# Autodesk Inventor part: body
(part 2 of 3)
sketch "Sketch106"
  geometry: L1 (112.535, 34.634)-(92.5, 34.634) reference; L2 (92.5, 34.634)-(74.5, 34.634) reference; L3 (74.5, 34.634)-(74.5, 30.196) reference; L4 (134.5, 30.196)-(74.5, 30.196) reference; L5 (134.5, 30.196)-(134.5, 10.853) reference; L6 (134.5, 10.853)-(131.5, 10.853) reference; L7 (131.5, 10.853)-(9.5, 10.853) reference; L8 (9.5, 10.853)-(6.5, 10.853) reference; L9 (6.5, 10.853)-(6.5, 30.196) reference; L10 (66.5, 30.196)-(6.5, 30.196) reference; L11 (66.5, 30.196)-(66.5, 34.634) reference; L12 (66.5, 34.634)-(48.5, 34.634) reference; L13 (48.5, 34.634)-(28.5, 34.634) reference; L14 (28.5, 34.634)-(28.5, 41.393) reference; L15 (28.5, 41.393)-(26.5, 41.393) reference; L16 (26.5, 41.393)-(26.5, 57.363) reference; L17 (26.5, 57.363)-(25.5, 57.363) reference; L18 (25.5, 57.363)-(25.5, 59.786) reference; L19 (25.5, 59.786)-(22.531, 56.13) reference; L20 (22.531, 56.13)-(18.537, 61.042) reference; L21 (18.537, 61.042)-(16.572, 63.459) reference; L22 (21.463, 69.48)-(16.572, 63.459) reference; L23 (22.049, 70.202)-(21.463, 69.48) reference; L24 (27.031, 76.338)-(22.049, 70.202) reference; L25 (27.852, 77.348)-(27.031, 76.338) reference; L26 (33.05, 83.749)-(27.852, 77.348) reference; L27 (33.757, 84.619)-(33.05, 83.749) reference; L28 (38.706, 90.712)-(33.757, 84.619) reference; L29 (39.413, 91.583)-(38.706, 90.712) reference; L30 (45.068, 98.547)-(39.413, 91.583) reference; L31 (45.775, 99.417)-(45.068, 98.547) reference; L32 (51.007, 105.86)-(45.775, 99.417) reference; L33 (51.711, 106.726)-(51.007, 105.86) reference; L34 (57.086, 113.344)-(51.711, 106.726) reference; L35 (57.793, 114.215)-(57.086, 113.344) reference; L36 (63.448, 121.179)-(57.793, 114.215) reference; L37 (64.155, 122.049)-(63.448, 121.179) reference; L38 (70.517, 129.883)-(64.155, 122.049) reference; L39 (70.517, 129.883)-(76.883, 122.053) reference; L40 (76.883, 122.053)-(77.59, 121.183) reference; L41 (77.59, 121.183)-(83.249, 114.223) reference; L42 (83.249, 114.223)-(83.956, 113.353) reference; L43 (83.956, 113.353)-(89.33, 106.743) reference; L44 (89.33, 106.743)-(90.037, 105.873) reference; L45 (90.037, 105.873)-(95.272, 99.433) reference; L46 (95.272, 99.433)-(95.98, 98.563) reference; L47 (95.98, 98.563)-(101.594, 91.656) reference; L48 (101.594, 91.656)-(102.302, 90.786) reference; L49 (102.302, 90.786)-(107.296, 84.642) reference; L50 (107.296, 84.642)-(108.004, 83.772) reference; L51 (108.004, 83.772)-(113.283, 77.279) reference; L52 (113.283, 77.279)-(113.99, 76.409) reference; L53 (113.99, 76.409)-(119.036, 70.202) reference; L54 (119.036, 70.202)-(119.743, 69.332) reference; L55 (119.743, 69.332)-(124.5, 63.48) reference; L56 (124.5, 63.48)-(122.529, 61.052) reference; L57 (122.529, 61.052)-(118.531, 56.13) reference; L58 (118.531, 56.13)-(115.5, 59.858) reference; L59 (115.5, 59.858)-(115.5, 56.973) reference; L60 (115.5, 56.973)-(114.5, 56.973) reference; L61 (114.5, 56.973)-(114.5, 41.452) reference; L62 (114.5, 41.452)-(112.535, 41.452) reference; L63 (112.535, 41.452)-(112.535, 34.634) reference; L64 (141, 136)-(0, 136)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; 3 further points
  constraints: 146 end point, 46 horizontal, 26 point on line, 15 parallel, 11 perpendicular, 2 midpoint, 78 other
extrude "Extrusion106" cut sketch "Sketch106" distance "d229" = 0.5; taper "d230" = 0 deg
sketch "Sketch107"
  geometry: L1 (0, -7.179)-(141, -7.179); L2 (141, -8)-(0, -8); L3 (0, -14)-(141, -14); L4 (141, -15.001)-(0, -15.001); L5 (0, -20.711)-(141, -20.711); L6 (141, -21.45)-(0, -21.45); L7 (0, -28.164)-(141, -28.164); L8 (141, -29.014)-(0, -29.014); L9 (0, -35.384)-(141, -35.384); L10 (141, -36.288)-(0, -36.288); 5 further points
  constraints: 20 end point, 10 horizontal, 22 other
extrude "Extrusion107" cut sketch "Sketch107" distance "d231" = 0.5; taper "d232" = 0 deg
sketch "Sketch108"
  geometry: L1 (0, -7.421)-(141, -7.421) reference; L2 (141, 0)-(0, 0) reference; L3 (7.47, 0)-(7.854, 0); L4 (7.854, 0)-(7.854, -7.421); L5 (7.854, -7.421)-(7.47, -7.421); L6 (7.47, -7.421)-(7.47, 0); L7 (15.615, 0)-(16, 0); L8 (16, 0)-(16, -7.421); L9 (16, -7.421)-(15.615, -7.421); L10 (15.615, -7.421)-(15.615, 0); L11 (23.615, 0)-(24, 0); L12 (24, 0)-(24, -7.421); L13 (24, -7.421)-(23.615, -7.421); L14 (23.615, -7.421)-(23.615, 0); L15 (31.615, 0)-(32, 0); L16 (32, 0)-(32, -7.421); L17 (32, -7.421)-(31.615, -7.421); L18 (31.615, -7.421)-(31.615, 0); L19 (39.615, 0)-(40, 0); L20 (40, 0)-(40, -7.421); L21 (40, -7.421)-(39.615, -7.421); L22 (39.615, -7.421)-(39.615, 0); L23 (47.615, 0)-(48, 0); L24 (48, 0)-(48, -7.421); L25 (48, -7.421)-(47.615, -7.421); L26 (47.615, -7.421)-(47.615, 0); L27 (55.615, 0)-(56, 0); L28 (56, 0)-(56, -7.421); L29 (56, -7.421)-(55.615, -7.421); L30 (55.615, -7.421)-(55.615, 0); L31 (63.615, 0)-(64, 0); L32 (64, 0)-(64, -7.421); L33 (64, -7.421)-(63.615, -7.421); L34 (63.615, -7.421)-(63.615, 0); L35 (71.615, 0)-(72, 0); L36 (72, 0)-(72, -7.421); L37 (72, -7.421)-(71.615, -7.421); L38 (71.615, -7.421)-(71.615, 0); L39 (79.615, 0)-(80, 0); L40 (80, 0)-(80, -7.421); L41 (80, -7.421)-(79.615, -7.421); L42 (79.615, -7.421)-(79.615, 0); L43 (87.615, 0)-(88, 0); L44 (88, 0)-(88, -7.421); L45 (88, -7.421)-(87.615, -7.421); L46 (87.615, -7.421)-(87.615, 0); L47 (95.615, 0)-(96, 0); L48 (96, 0)-(96, -7.421); L49 (96, -7.421)-(95.615, -7.421); L50 (95.615, -7.421)-(95.615, 0); L51 (103.615, 0)-(104, 0); L52 (104, 0)-(104, -7.421); L53 (104, -7.421)-(103.615, -7.421); L54 (103.615, -7.421)-(103.615, 0); L55 (111.615, 0)-(112, 0); L56 (112, 0)-(112, -7.421); L57 (112, -7.421)-(111.615, -7.421); L58 (111.615, -7.421)-(111.615, 0); L59 (119.615, 0)-(120, 0); L60 (120, 0)-(120, -7.421); L61 (120, -7.421)-(119.615, -7.421); L62 (119.615, -7.421)-(119.615, 0); L63 (126.62, 0)-(127.004, 0); L64 (127.004, 0)-(127.004, -7.421)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; 1 further point
  constraints: 136 end point, 34 parallel, 17 horizontal, 17 perpendicular, 2 point on line
extrude "Extrusion108" cut sketch "Sketch108" distance "d233" = 0.5; taper "d234" = 0 deg
sketch "Sketch109"
  geometry: L1 (6.945, 6.642)-(7.33, 6.642); L2 (7.33, 6.642)-(7.33, 0); L3 (7.33, 0)-(6.945, 0); L4 (6.945, 0)-(6.945, 6.642); L5 (13.996, 6.642)-(14.38, 6.642); L6 (14.38, 6.642)-(14.38, 0); L7 (14.38, 0)-(13.996, 0); L8 (13.996, 0)-(13.996, 6.642); L9 (21, 6.642)-(21.385, 6.642); L10 (21.385, 6.642)-(21.385, 0); L11 (21.385, 0)-(21, 0); L12 (21, 0)-(21, 6.642); L13 (29, 6.642)-(29.385, 6.642); L14 (29.385, 6.642)-(29.385, 0); L15 (29.385, 0)-(29, 0); L16 (29, 0)-(29, 6.642); L17 (37, 6.642)-(37.385, 6.642); L18 (37.385, 6.642)-(37.385, 0); L19 (37.385, 0)-(37, 0); L20 (37, 0)-(37, 6.642); L21 (45, 6.642)-(45.385, 6.642); L22 (45.385, 6.642)-(45.385, 0); L23 (45.385, 0)-(45, 0); L24 (45, 0)-(45, 6.642); L25 (53, 6.642)-(53.385, 6.642); L26 (53.385, 6.642)-(53.385, 0); L27 (53.385, 0)-(53, 0); L28 (53, 0)-(53, 6.642); L29 (61, 6.642)-(61.385, 6.642); L30 (61.385, 6.642)-(61.385, 0); L31 (61.385, 0)-(61, 0); L32 (61, 0)-(61, 6.642); L33 (69, 6.642)-(69.385, 6.642); L34 (69.385, 6.642)-(69.385, 0); L35 (69.385, 0)-(69, 0); L36 (69, 0)-(69, 6.642); L37 (77, 6.642)-(77.385, 6.642); L38 (77.385, 6.642)-(77.385, 0); L39 (77.385, 0)-(77, 0); L40 (77, 0)-(77, 6.642); L41 (85, 6.642)-(85.385, 6.642); L42 (85.385, 6.642)-(85.385, 0); L43 (85.385, 0)-(85, 0); L44 (85, 0)-(85, 6.642); L45 (93, 6.642)-(93.385, 6.642); L46 (93.385, 6.642)-(93.385, 0); L47 (93.385, 0)-(93, 0); L48 (93, 0)-(93, 6.642); L49 (101, 6.642)-(101.385, 6.642); L50 (101.385, 6.642)-(101.385, 0); L51 (101.385, 0)-(101, 0); L52 (101, 0)-(101, 6.642); L53 (109, 6.642)-(109.385, 6.642); L54 (109.385, 6.642)-(109.385, 0); L55 (109.385, 0)-(109, 0); L56 (109, 0)-(109, 6.642); L57 (117, 6.642)-(117.385, 6.642); L58 (117.385, 6.642)-(117.385, 0); L59 (117.385, 0)-(117, 0); L60 (117, 0)-(117, 6.642); L61 (125, 6.642)-(125.385, 6.642); L62 (125.385, 6.642)-(125.385, 0); L63 (125.385, 0)-(125, 0); L64 (125, 0)-(125, 6.642)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; 3 further points
  constraints: 136 end point, 34 parallel, 17 horizontal, 17 perpendicular, 18 other
extrude "Extrusion109" cut sketch "Sketch109" distance "d235" = 0.5; taper "d236" = 0 deg
fillet "Fillet1" dims "d237" = 1.5
sketch "Sketch110"
  geometry: L1 (-25.92, 44.197)-(-26.502, 43.385) reference; L2 (-105.601, -66.016)-(-100, -70.035) reference; L3 (-100, -70.035)-(-22, 38.693) reference; L4 (0, 4.693)-(0, 16.519) reference; L5 (-2.706, 19.781)-(-3.198, 20.54) reference; L6 (-18.1, 44.492)-(-20.805, 48.671) reference; L7 (-2.706, 19.781)-(0, 15.598); L8 (-3.198, 20.54)-(-21.049, 48.128); L9 (-21.888, 48.585)-(-22.259, 48.585); L10 (-23.071, 48.168)-(-25.92, 44.197); L11 (-26.502, 43.385)-(-105.195, -66.308); L12 (-104.917, -66.507)-(-22.881, 47.846); L13 (-22.068, 48.263)-(-22.042, 48.263); L14 (-21.203, 47.806)-(0, 15.038); A1 r 1 centre (-22.068, 47.263) between (-22.068, 48.263) and (-22.881, 47.846); A2 r 1 centre (-22.042, 47.263) between (-21.203, 47.806) and (-22.042, 48.263); A3 r 1 centre (-21.888, 47.585) between (-21.049, 48.128) and (-21.888, 48.585); A4 r 1 centre (-22.259, 47.585) between (-22.259, 48.585) and (-23.071, 48.168); 1 further point
  constraints: 16 end point, 8 point on circle, 8 tangent, 5 parallel, 4 centre point, 4 point on line, 3 equal radius, 2 perpendicular, 1 collinear
  dimensions: "d238" = 1 radius of A1
extrude "Extrusion110" cut sketch "Sketch110" distance "d239" = 0.5; taper "d240" = 0 deg
sketch "Sketch111"
  geometry: L1 (-66.098, 27.153)-(-66.684, 26.567) reference; L2 (-71.928, 22.028)-(-67.998, 18.1) reference; L3 (32.057, 18.1)-(36, 22.045) reference; L4 (-11.617, 69.638)-(-17.983, 76) reference; L5 (-66.684, 26.567)-(-71.574, 21.674); L6 (-66.098, 27.153)-(-19.397, 73.878); L7 (-16.568, 73.879)-(35.646, 21.691); L8 (35.415, 21.459)-(-16.585, 73.432); L9 (-19.413, 73.432)-(-71.359, 21.459); L10 (-71.574, 21.674)-(-71.359, 21.459); A1 r 2 centre (-17.999, 72.018) between (-16.585, 73.432) and (-19.413, 73.432); A2 r 2 centre (-17.982, 72.464) between (-16.568, 73.879) and (-19.397, 73.878); 1 further point
  constraints: 12 end point, 5 perpendicular, 4 point on circle, 4 point on line, 4 tangent, 2 centre point, 1 collinear, 1 equal radius
  dimensions: "d241" = 2 radius of A1
extrude "Extrusion111" cut sketch "Sketch111" distance "d242" = 0.5; taper "d243" = 0 deg
sketch "Sketch112"
  geometry: L1 (9, 0)-(9, 60.457) reference; L2 (2.125, 63.944)-(9, 60.457) reference; L3 (0, 65.022)-(0, 0) reference; L4 (9, 0)-(0, 0) reference; L5 (9, 6)-(0, 6); L6 (0, 6)-(0, 6.417); L7 (0, 6.417)-(9, 6.417); L8 (9, 6.417)-(9, 6); L9 (9, 12.583)-(0, 12.583); L10 (0, 12.583)-(0, 13); L11 (0, 13)-(9, 13); L12 (9, 13)-(9, 12.583); L13 (9, 19.583)-(0, 19.583); L14 (0, 19.583)-(0, 20); L15 (0, 20)-(9, 20); L16 (9, 20)-(9, 19.583); L17 (9, 26.583)-(0, 26.583); L18 (0, 26.583)-(0, 27); L19 (0, 27)-(9, 27); L20 (9, 27)-(9, 26.583); L21 (9, 33.583)-(0, 33.583); L22 (0, 33.583)-(0, 34); L23 (0, 34)-(9, 34); L24 (9, 34)-(9, 33.583); L25 (9, 40.583)-(0, 40.583); L26 (0, 40.583)-(0, 41); L27 (0, 41)-(9, 41); L28 (9, 41)-(9, 40.583); L29 (9, 47.519)-(0, 47.519); L30 (0, 47.519)-(0, 47.936); L31 (0, 47.936)-(9, 47.936); L32 (9, 47.936)-(9, 47.519); L33 (9, 54.413)-(0, 54.413); L34 (0, 54.413)-(0, 54.83); L35 (0, 54.83)-(9, 54.83); L36 (9, 54.83)-(9, 54.413); L37 (7.718, 61.108)-(0, 61.108); L38 (0, 61.108)-(0, 61.429); L39 (0, 61.429)-(7.085, 61.429); 1 further point
  constraints: 70 end point, 18 parallel, 9 horizontal, 9 perpendicular, 4 point on line
extrude "Extrusion112" cut sketch "Sketch112" distance "d244" = 0.5; taper "d245" = 0 deg
sketch "Sketch113"
  geometry: L1 (-0.653, 8.5)-(-0.974, 8.5) reference; L2 (-3.422, 6.744)-(0, 0) reference; L3 (0, 0)-(60.455, 0) reference; L4 (12.936, 9)-(19.455, 9) reference; L5 (-0.974, 8.5)-(-0.974, 1.919); L6 (5.625, 8.5)-(6.042, 8.5); L7 (6.042, 8.5)-(6.042, 0); L8 (6.042, 0)-(5.625, 0); L9 (5.625, 0)-(5.625, 8.5); L10 (12.519, 8.5)-(12.936, 8.5); L11 (12.936, 8.5)-(12.936, 0); L12 (12.936, 0)-(12.519, 0); L13 (12.519, 0)-(12.519, 8.5); L14 (19.455, 8.5)-(19.872, 8.5); L15 (19.872, 8.5)-(19.872, 0); L16 (19.872, 0)-(19.455, 0); L17 (19.455, 0)-(19.455, 8.5); L18 (26.455, 8.5)-(26.883, 8.5); L19 (26.883, 0)-(26.455, 0); L20 (34, 0)-(33.455, 0); L21 (41, 0)-(40.455, 0); L22 (47.455, 8.5)-(47.872, 8.5); L23 (47.872, 8.5)-(47.872, 0); L24 (47.872, 0)-(47.455, 0); L25 (47.455, 0)-(47.455, 8.5); L26 (54.038, 8.5)-(54.455, 8.5); L27 (54.455, 8.5)-(54.455, 0); L28 (54.455, 0)-(54.038, 0); L29 (54.038, 0)-(54.038, 8.5); L30 (-0.653, 8.5)-(-0.653, 1.286); L31 (26.455, 8.5)-(26.883, 8.5); L32 (26.883, 8.5)-(26.883, 0); L33 (26.883, 0)-(26.455, 0); L34 (26.455, 0)-(26.455, 8.5); L35 (33.455, 8.5)-(33.872, 8.5); L36 (33.872, 8.5)-(33.872, 0); L37 (33.872, 0)-(33.455, 0); L38 (33.455, 0)-(33.455, 8.5); L39 (40.455, 8.5)-(40.872, 8.5); L40 (40.872, 8.5)-(40.872, 0); L41 (40.872, 0)-(40.455, 0); L42 (40.455, 0)-(40.455, 8.5); 1 further point
  constraints: 76 end point, 18 parallel, 9 horizontal, 9 perpendicular, 9 point on line
extrude "Extrusion113" cut sketch "Sketch113" distance "d246" = 0.5; taper "d247" = 0 deg
fillet "Fillet2" dims "d248" = 1.5
fillet "Fillet3" dims "d249" = 0.5, "d250" = 1.5
sketch "Sketch114"
  geometry: L1 (7, -17.145)-(7, -25.258) reference; L2 (1, -25.258)-(1, -17.145) reference; L3 (-60, -50.112)-(-60, 7.159) reference; L4 (68, 7.159)-(68, -50.112) reference; L5 (-60, 0)-(68, 0); L6 (68, 0)-(68, -1); L7 (68, -1)-(-60, -1); L8 (-60, -1)-(-60, 0); L9 (-60, -9)-(68, -9); L10 (68, -9)-(68, -10); L11 (68, -10)-(-60, -10); L12 (-60, -10)-(-60, -9); L13 (-60, -18)-(1, -18); L14 (1, -18)-(1, -19); L15 (1, -19)-(-60, -19); L16 (-60, -19)-(-60, -18); L17 (7, -18)-(68, -18); L18 (68, -18)-(68, -19); L19 (68, -19)-(7, -19); L20 (7, -19)-(7, -18); L21 (-60, -27)-(68, -27); L22 (68, -27)-(68, -28); L23 (68, -28)-(-60, -28); L24 (-60, -28)-(-60, -27); L25 (-60, -36)-(68, -36); L26 (68, -36)-(68, -37); L27 (68, -37)-(-60, -37); L28 (-60, -37)-(-60, -36); L29 (-60, -45)-(68, -45); L30 (68, -45)-(68, -46); L31 (68, -46)-(-60, -46); L32 (-60, -46)-(-60, -45); 1 further point
  constraints: 56 end point, 14 parallel, 14 point on line, 7 horizontal, 7 perpendicular
extrude "Extrusion114" cut sketch "Sketch114" distance "d251" = 0.5; taper "d252" = 0 deg
sketch "Sketch115"
  geometry: L1 (-119.015, -55.796)-(-118.805, -56.25) reference; L2 (-118.805, -56.25)-(-119.713, -56.669) reference; L3 (-119.713, -56.669)-(-119.923, -56.215) reference; L4 (-119.923, -56.215)-(-127.187, -59.567) reference; L5 (-127.187, -59.567)-(-126.977, -60.021) reference; L6 (-126.977, -60.021)-(-127.885, -60.44) reference; L7 (-127.885, -60.44)-(-128.094, -59.986) reference; L8 (-128.094, -59.986)-(-135.358, -63.339) reference; L9 (-135.358, -63.339)-(-135.149, -63.793) reference; L10 (-135.149, -63.793)-(-136.057, -64.212) reference; L11 (-136.057, -64.212)-(-136.266, -63.758) reference; L12 (-136.266, -63.758)-(-140, -65.481) reference; L13 (-140, -65.481)-(-136, -74.148) reference; L14 (-94.526, -50.578)-(-98.786, -56.517) reference; L15 (-94.526, -50.578)-(-94.12, -50.87) reference; L16 (-94.12, -50.87)-(-93.537, -50.057) reference; L17 (-93.943, -49.766)-(-93.537, -50.057) reference; L18 (-89.863, -44.078)-(-93.943, -49.766) reference; L19 (-89.863, -44.078)-(-89.457, -44.369) reference; L20 (-89.457, -44.369)-(-88.874, -43.557) reference; L21 (-89.28, -43.265)-(-88.874, -43.557) reference; L22 (-88, -41.481)-(-89.28, -43.265) reference; L23 (-88, -41.481)-(-94.5, -44.481) reference; L24 (-94.5, -44.481)-(-94.29, -44.935) reference; L25 (-94.29, -44.935)-(-95.198, -45.354) reference; L26 (-95.198, -45.354)-(-95.408, -44.9) reference; L27 (-95.408, -44.9)-(-102.672, -48.253) reference; L28 (-102.672, -48.253)-(-102.462, -48.707) reference; L29 (-102.462, -48.707)-(-103.37, -49.126) reference; L30 (-103.37, -49.126)-(-103.58, -48.672) reference; L31 (-103.58, -48.672)-(-110.843, -52.024) reference; L32 (-110.843, -52.024)-(-110.634, -52.478) reference; L33 (-110.634, -52.478)-(-111.542, -52.897) reference; L34 (-111.542, -52.897)-(-111.751, -52.443) reference; L35 (-111.751, -52.443)-(-119.015, -55.796) reference; L36 (-137, -71.981)-(-96.656, -53.547); 1 further point
  constraints: 2 end point, 1 midpoint, 1 point on line
extrude "Extrusion115" join sketch "Sketch115" distance "d253" = 0.5; taper "d254" = 0 deg
sketch "Sketch116"
  geometry: L1 (118.805, -56.233)-(119.015, -55.779) reference; L2 (119.015, -55.779)-(111.751, -52.427) reference; L3 (111.751, -52.427)-(111.542, -52.881) reference; L4 (111.542, -52.881)-(110.634, -52.462) reference; L5 (110.634, -52.462)-(110.843, -52.008) reference; L6 (110.843, -52.008)-(103.58, -48.655) reference; L7 (103.58, -48.655)-(103.37, -49.109) reference; L8 (103.37, -49.109)-(102.462, -48.69) reference; L9 (102.462, -48.69)-(102.672, -48.236) reference; L10 (102.672, -48.236)-(95.408, -44.884) reference; L11 (95.408, -44.884)-(95.198, -45.338) reference; L12 (95.198, -45.338)-(94.29, -44.919) reference; L13 (94.29, -44.919)-(94.5, -44.465) reference; L14 (94.5, -44.465)-(88, -41.465) reference; L15 (89.28, -43.249)-(88, -41.465) reference; L16 (89.28, -43.249)-(88.874, -43.54) reference; L17 (88.874, -43.54)-(89.457, -44.353) reference; L18 (89.863, -44.061)-(89.457, -44.353) reference; L19 (93.943, -49.749)-(89.863, -44.061) reference; L20 (93.943, -49.749)-(93.537, -50.041) reference; L21 (93.537, -50.041)-(94.12, -50.853) reference; L22 (94.526, -50.562)-(94.12, -50.853) reference; L23 (98.786, -56.5)-(94.526, -50.562) reference; L24 (136, -74.131)-(140, -65.465) reference; L25 (140, -65.465)-(136.266, -63.741) reference; L26 (136.266, -63.741)-(136.057, -64.195) reference; L27 (136.057, -64.195)-(135.149, -63.776) reference; L28 (135.149, -63.776)-(135.358, -63.322) reference; L29 (135.358, -63.322)-(128.094, -59.97) reference; L30 (128.094, -59.97)-(127.885, -60.424) reference; L31 (127.885, -60.424)-(126.977, -60.005) reference; L32 (126.977, -60.005)-(127.187, -59.551) reference; L33 (127.187, -59.551)-(119.923, -56.198) reference; L34 (119.923, -56.198)-(119.713, -56.652) reference; L35 (119.713, -56.652)-(118.805, -56.233) reference; L36 (136.984, -72)-(96.656, -53.531); 1 further point
  constraints: 2 end point, 1 midpoint, 1 point on line
extrude "Extrusion116" join sketch "Sketch116" distance "d255" = 0.5; taper "d256" = 0 deg
sketch "Sketch117"
  geometry: L1 (89.28, -43.249)-(88, -41.465) reference; L2 (136.984, -72)-(140, -65.465) reference; L3 (136.057, -64.195)-(135.149, -63.776) reference; L4 (136.057, -64.195)-(139.79, -65.919); L5 (139.565, -66.408)-(89.28, -43.249); L6 (119.713, -56.652)-(118.805, -56.233) reference; L7 (135.149, -63.776)-(88.591, -42.288); L8 (88.591, -42.288)-(89.28, -43.249); 2 further points
  constraints: 8 end point, 3 point on line, 2 collinear, 1 midpoint, 1 perpendicular
extrude "Extrusion117" cut sketch "Sketch117" distance "d257" = 0.5; taper "d258" = 0 deg
sketch "Sketch118"
  geometry: L1 (-135.149, -63.793)-(-136.057, -64.212) reference; L2 (-140, -65.481)-(-137, -71.981) reference; L3 (-88, -41.481)-(-89.28, -43.265) reference; L4 (-136.057, -64.212)-(-139.79, -65.935); L5 (-135.149, -63.793)-(-88.487, -42.159); L6 (-139.571, -66.412)-(-89.098, -43.012); 1 further point
  constraints: 6 end point, 4 point on line, 1 parallel, 1 perpendicular
extrude "Extrusion118" cut sketch "Sketch118" distance "d259" = 0.5; taper "d260" = 0 deg
sketch "Sketch119"
  geometry: L1 (125, 1.52)-(125, 2.045) reference; L2 (-3, 2.045)-(-3, 1.507) reference; L3 (125, 1.52)-(-3, 1.507); L4 (-3, 2.045)-(125, 2.045); 1 further point
  constraints: 4 end point
extrude "Extrusion119" cut sketch "Sketch119" distance "d261" = 0.5; taper "d262" = 0 deg
sketch "Sketch120"
  geometry: L1 (0, 16.535)-(0, 3.214) reference; L2 (0, 3.214)-(22.527, 38.028) reference; L3 (100.026, -70)-(105.601, -66) reference; L4 (102.863, -63.041)-(102.281, -62.229) reference; L5 (102.863, -63.041)-(105.195, -66.291); L6 (102.281, -62.229)-(25.92, 44.214); L7 (18.52, 44.237)-(0, 15.615); L8 (0, 15)-(21.239, 47.824); L9 (22.078, 48.28)-(22.106, 48.28); L10 (22.918, 47.863)-(104.942, -66.473); L11 (18.52, 44.237)-(21.04, 48.131); L12 (21.879, 48.587)-(22.269, 48.587); L13 (23.081, 48.17)-(25.92, 44.214); A1 r 1 centre (22.078, 47.28) between (22.078, 48.28) and (21.239, 47.824); A2 r 1 centre (22.106, 47.28) between (22.918, 47.863) and (22.106, 48.28); A3 r 1 centre (22.269, 47.587) between (23.081, 48.17) and (22.269, 48.587); A4 r 1 centre (21.879, 47.587) between (21.879, 48.587) and (21.04, 48.131); 1 further point
  constraints: 18 end point, 8 point on circle, 8 tangent, 5 parallel, 4 centre point, 4 point on line, 3 equal radius, 3 perpendicular, 1 collinear
  dimensions: "d263" = 1 radius of A1
extrude "Extrusion120" cut sketch "Sketch120" distance "d264" = 0.5; taper "d265" = 0 deg
sketch "Sketch121"
  geometry: L1 (0, -0.5)-(0.5, -0.5) reference; L2 (0.5, -0.5)-(0.5, -0.811) reference; L3 (140.5, -0.842)-(140.5, -0.5) reference; L4 (0.5, -0.811)-(140.5, -0.842); L5 (140.5, -0.5)-(0.5, -0.5); 1 further point
  constraints: 4 end point, 1 collinear
extrude "Extrusion121" cut sketch "Sketch121" distance "d266" = 0.5; taper "d267" = 0 deg
sketch "Sketch122"
  geometry: L1 (125, 0)-(3, 0) reference; L2 (3, 7)-(125, 7) reference; L3 (64, 7)-(62, 7); L4 (62, 7)-(62, 0); L5 (62, 0)-(64, 0); L6 (64, 0)-(64, 7); L7 (64, 0)-(66, 0); L8 (66, 0)-(66, 7); L9 (66, 7)-(64, 7); L10 (64, 7)-(64, 0); L11 (93, 0)-(97, 0); L12 (97, 0)-(97, 7); L13 (97, 7)-(93, 7); L14 (93, 7)-(93, 0); L15 (34, 0)-(30, 0); L16 (30, 0)-(30, 7); L17 (30, 7)-(34, 7); L18 (34, 7)-(34, 0); 1 further point
  constraints: 32 end point, 8 parallel, 6 point on line, 4 horizontal, 4 perpendicular, 1 midpoint
extrude "Extrusion122" join sketch "Sketch122" distance "d268" = 40.5; taper "d269" = 0 deg
sketch "Sketch123"
  geometry: L1 (10.316, 6)-(129.684, 6) reference; L2 (129.684, 0)-(10.316, 0) reference; L3 (103, 6)-(99, 6); L4 (99, 6)-(99, 0); L5 (99, 0)-(103, 0); L6 (103, 0)-(103, 6); L7 (72, 6)-(68, 6); L8 (68, 6)-(68, 0); L9 (68, 0)-(72, 0); L10 (72, 0)-(72, 6); L11 (40, 6)-(36, 6); L12 (36, 6)-(36, 0); L13 (36, 0)-(40, 0); L14 (40, 0)-(40, 6); 1 further point
  constraints: 24 end point, 6 parallel, 5 point on line, 3 horizontal, 3 perpendicular
extrude "Extrusion123" join sketch "Sketch123" distance "d270" = 12.5; taper "d271" = 0 deg
sketch "Sketch124"
  geometry: L1 (126.488, 149.508)-(100, 149.508); L2 (100, 149.508)-(100, 118); L3 (100, 118)-(126.488, 118); L4 (126.488, 118)-(126.488, 149.508); 1 further point
  constraints: 8 end point, 2 parallel, 1 horizontal, 1 perpendicular
extrude "Extrusion124" cut sketch "Sketch124" distance "d272" = 7.25; taper "d273" = 0 deg
sketch "Sketch125"
  geometry: L1 (-113.739, 149.54)-(-132.244, 149.54); L2 (-132.244, 149.54)-(-132.244, 117.97); L3 (-132.244, 117.97)-(-113.739, 117.97); L4 (-113.739, 117.97)-(-113.739, 149.54); 1 further point
  constraints: 8 end point, 2 parallel, 1 horizontal, 1 perpendicular
extrude "Extrusion125" cut sketch "Sketch125" distance "d274" = 8.75; taper "d275" = 0 deg
sketch "Sketch126"
  geometry: L1 (100, 118)-(100, 149.508) reference; L2 (126.488, 149.508)-(126.488, 118) reference; L3 (126.488, 118)-(100, 118) reference; L4 (136, 113)-(136, 155.663) reference; L5 (100, 149.508)-(95.736, 149.508); L6 (95.736, 149.508)-(95.736, 115.93); L7 (95.736, 115.93)-(130.926, 115.93); L8 (130.926, 115.93)-(130.926, 149.508); L9 (130.926, 149.508)-(126.488, 149.508); 1 further point
  constraints: 10 end point, 2 parallel, 2 perpendicular, 1 collinear
extrude "Extrusion126" join sketch "Sketch126" distance "d276" = 4.5; taper "d277" = 0 deg
sketch "Sketch127"
  geometry: L1 (-132.244, 117.97)-(-132.244, 149.54) reference; L2 (-113.739, 149.54)-(-113.739, 117.97) reference; L3 (-113.739, 117.97)-(-132.244, 117.97) reference; L4 (-111.755, 115.96)-(-111.755, 149.54); L5 (-111.755, 149.54)-(-113.739, 149.54); L6 (-134.122, 149.54)-(-134.122, 115.96); L7 (-134.122, 149.54)-(-132.244, 149.54); L8 (-134.122, 115.96)-(-111.755, 115.96); 1 further point
  constraints: 10 end point, 1 parallel, 1 perpendicular
extrude "Extrusion127" join sketch "Sketch127" distance "d278" = 4.5; taper "d279" = 0 deg
sketch "Sketch128"
  geometry: L1 (0, 15)-(0, 3.214) reference; L2 (0, 3.214)-(22.527, 38.028) reference; L3 (22.527, 38.028)-(100.026, -70) reference; L4 (100.026, -70)-(104.942, -66.473) reference; L5 (17.818, 30.751)-(27.748, 30.751); L6 (17.818, 30.751)-(13.512, 33.537); L7 (13.512, 33.537)-(20.328, 44.07); L8 (20.328, 44.07)-(24.103, 44.07); L9 (24.103, 44.07)-(31.759, 33.397); L10 (31.759, 33.397)-(27.858, 30.598); 1 further point
  constraints: 12 end point, 5 perpendicular, 3 point on line, 1 parallel
extrude "Extrusion128" join sketch "Sketch128" distance "d280" = 12.75; taper "d281" = 0 deg
sketch "Sketch129"
  geometry: L1 (-100, -70.035)-(-22, 38.693) reference; L2 (-22, 38.693)-(0, 4.693) reference; L3 (0, 15.038)-(-21.203, 47.806) reference; L4 (-22.042, 48.263)-(-22.068, 48.263) reference; L5 (-27.567, 30.933)-(-16.979, 30.933); L6 (-16.979, 30.933)-(-13.376, 33.264); L7 (-13.376, 33.264)-(-18.621, 41.7); L8 (-18.621, 41.7)-(-25.983, 42.207); L9 (-25.983, 42.207)-(-31.861, 34.014); L10 (-31.861, 34.014)-(-27.567, 30.933); 1 further point
  constraints: 12 end point, 2 parallel, 2 perpendicular, 2 point on line
extrude "Extrusion129" join sketch "Sketch129" distance "d282" = 12.75; taper "d283" = 0 deg
chamfer "Chamfer3" distance "d284" = 10.75; stored, may be unused: second distance "d285" = 2, angle "d286" = 45 deg
chamfer "Chamfer4" distance "d287" = 3.25; stored, may be unused: second distance "d288" = 2, angle "d289" = 45 deg
sketch "Sketch130"
  geometry: L1 (-19.332, 32.944)-(-25.465, 32.944); L2 (-25.465, 32.944)-(-25.465, 40.232); L3 (-25.465, 40.232)-(-19.332, 40.232); L4 (-19.332, 40.232)-(-19.332, 32.944); 1 further point
  constraints: 8 end point, 2 parallel, 1 horizontal, 1 perpendicular
extrude "Extrusion130" cut sketch "Sketch130" distance "d290" = 6; taper "d291" = 0 deg
sketch "Sketch131"
  geometry: L1 (25.463, 32.966)-(19.276, 32.966); L2 (19.276, 32.966)-(19.276, 40.234); L3 (19.276, 40.234)-(25.463, 40.234); L4 (25.463, 40.234)-(25.463, 32.966); 1 further point
  constraints: 8 end point, 2 parallel, 1 horizontal, 1 perpendicular
extrude "Extrusion131" cut sketch "Sketch131" distance "d292" = 6; taper "d293" = 0 deg
chamfer "Chamfer5" distance "d294" = 1; stored, may be unused: second distance "d295" = 2, angle "d296" = 45 deg
sketch "Sketch132"
  geometry: L1 (-133.906, 118)-(-92.461, 118); L2 (-92.461, 118)-(-92.461, 112.056); L3 (-92.461, 112.056)-(-133.906, 112.056); L4 (-133.906, 112.056)-(-133.906, 118); 1 further point
  constraints: 8 end point, 2 parallel, 1 horizontal, 1 perpendicular
extrude "Extrusion132" join sketch "Sketch132" distance "d297" = 2.25; taper "d299" = 0 deg; dims "d298" = 1, "d300" = 0
sketch "Sketch133"
  geometry: L1 (110.885, 117.97)-(135.174, 117.97); L2 (135.174, 117.97)-(135.174, 112.894); L3 (135.174, 112.894)-(110.885, 112.894); L4 (110.885, 112.894)-(110.885, 117.97); 1 further point
  constraints: 8 end point, 2 parallel, 1 horizontal, 1 perpendicular
extrude "Extrusion133" join sketch "Sketch133" distance "d301" = 1.125; taper "d303" = 0 deg; dims "d302" = 2.25, "d304" = 0
sketch "Sketch134"
  geometry: L1 (-12.94, -20.948)-(0, -7.972) reference; L2 (-22.249, -7.972)-(0, -7.972) reference; L3 (-21.53, -8.974)-(-22.249, -7.972) reference; L4 (-21.53, -8.974)-(-21.936, -9.265) reference; L5 (-21.936, -9.265)-(-21.458, -9.933) reference; L6 (-21.051, -9.641)-(-21.458, -9.933) reference; L7 (-17.498, -14.594)-(-21.051, -9.641) reference; L8 (-17.498, -14.594)-(-17.904, -14.886) reference; L9 (-17.904, -14.886)-(-17.437, -15.537) reference; L10 (-17.031, -15.245)-(-17.437, -15.537) reference; L11 (-13.414, -20.288)-(-17.031, -15.245) reference; L12 (-7.078, -7.972)-(-15.901, -16.82); 1 further point
  constraints: 2 end point, 2 point on line, 1 parallel
extrude "Extrusion134" cut sketch "Sketch134" distance "d305" = 1; taper "d306" = 0 deg
sketch "Sketch135"
  geometry: L1 (22.022, -8.341)-(21.53, -9.026) reference; L2 (0.5, -8.341)-(22.022, -8.341) reference; L3 (0.5, -8.341)-(12.974, -20.952) reference; L4 (17.031, -15.297)-(13.414, -20.34) reference; L5 (17.031, -15.297)-(17.437, -15.589) reference; L6 (17.437, -15.589)-(17.904, -14.938) reference; L7 (17.498, -14.647)-(17.904, -14.938) reference; L8 (21.051, -9.693)-(17.498, -14.647) reference; L9 (21.458, -9.985)-(21.051, -9.693) reference; L10 (21.936, -9.317)-(21.458, -9.985) reference; L11 (21.53, -9.026)-(21.936, -9.317) reference; L12 (7.353, -8.341)-(15.855, -16.937); 1 further point
  constraints: 2 end point, 2 point on line, 1 parallel
extrude "Extrusion135" cut sketch "Sketch135" distance "d307" = 1; taper "d308" = 0 deg
sketch "Sketch136"
  geometry: L1 (4.179, -22.522)-(108.319, -22.522); L2 (108.319, -22.522)-(108.319, -14.938); L3 (108.319, -14.938)-(4.179, -14.938); L4 (4.179, -14.938)-(4.179, -22.522); 1 further point
  constraints: 8 end point, 2 parallel, 1 horizontal, 1 perpendicular
extrude "Extrusion136" join sketch "Sketch136" distance "d309" = 3.5; taper "d310" = 0 deg
sketch "Sketch137"
  geometry: L1 (26, -22.522)-(26, -55) reference; L2 (8, -55)-(8, -22.522) reference; L3 (8, -22.522)-(26, -22.522) reference; L4 (104, -22.522)-(104, -55) reference; L5 (86, -55)-(86, -22.522) reference; L6 (34, -22.522)-(78, -22.522) reference; L7 (78, -22.522)-(78, -66.522) reference; L8 (78, -66.522)-(112, -66.522) reference; L9 (0, -66.522)-(34, -66.522) reference; L10 (34, -66.522)-(34, -22.522) reference; L11 (6.079, -22.522)-(6.079, -55); L12 (6.079, -55)-(8, -55); L13 (26, -55)-(28.093, -55); L14 (28.093, -55)-(28.093, -22.522); L15 (28.093, -22.522)-(26, -22.522); L16 (6.079, -22.522)-(8, -22.522); L17 (30.443, -22.522)-(30.443, -66.522); L18 (81.695, -22.522)-(81.695, -66.522); L19 (86, -55)-(84.036, -55); L20 (84.036, -55)-(84.036, -22.522); L21 (84.036, -22.522)-(86, -22.522); L22 (104, -22.522)-(106.151, -22.522); L23 (106.151, -22.522)-(106.151, -55); L24 (106.151, -55)-(104, -55); L25 (30.443, -22.522)-(34, -22.522); L26 (78, -22.522)-(81.695, -22.522); 1 further point
  constraints: 32 end point, 7 perpendicular, 6 collinear, 3 parallel, 3 point on line
extrude "Extrusion137" join sketch "Sketch137" distance "d311" = 3; taper "d312" = 0 deg
sketch "Sketch138"
  geometry: L1 (26, -55)-(8, -55) reference; L2 (29.199, -55)-(4.639, -55); L3 (4.639, -55)-(4.639, -59.676); L4 (4.639, -59.676)-(29.199, -59.676); L5 (29.199, -59.676)-(29.199, -55); L6 (82.764, -55)-(107.626, -55); L7 (107.626, -55)-(107.626, -59.676); L8 (107.626, -59.676)-(82.764, -59.676); L9 (82.764, -59.676)-(82.764, -55); 1 further point
  constraints: 16 end point, 4 parallel, 2 horizontal, 2 perpendicular, 2 point on line
extrude "Extrusion138" join sketch "Sketch138" distance "d313" = 3.5; taper "d314" = 0 deg
chamfer "Chamfer6" distance "d315" = 2; stored, may be unused: second distance "d316" = 2, angle "d317" = 45 deg
chamfer "Chamfer7" distance "d318" = 2; stored, may be unused: second distance "d319" = 2, angle "d320" = 45 deg
chamfer "Chamfer8" distance "d321" = 1; stored, may be unused: second distance "d322" = 2, angle "d323" = 45 deg
chamfer "Chamfer9" distance "d324" = 2; stored, may be unused: second distance "d325" = 2, angle "d326" = 45 deg
sketch "Sketch139"
  geometry: L1 (10.58, -6.723)-(4.23, -6.723); L2 (4.23, -6.723)-(4.23, 0.37); L3 (4.23, 0.37)-(10.58, 0.37); L4 (10.58, 0.37)-(10.58, -6.723); L5 (16.518, -6.723)-(14.292, -6.723); L6 (14.292, -6.723)-(14.292, 0.37); L7 (14.292, 0.37)-(16.518, 0.37); L8 (16.518, 0.37)-(16.518, -6.723); L9 (31.858, 0.37)-(36.559, 0.37); L10 (36.559, 0.37)-(36.559, -6.723); L11 (36.559, -6.723)-(31.858, -6.723); L12 (31.858, -6.723)-(31.858, 0.37); L13 (44.559, -6.723)-(51.486, -6.723); L14 (51.486, -6.723)-(51.486, 0.37); L15 (51.486, 0.37)-(44.559, 0.37); L16 (44.559, 0.37)-(44.559, -6.723); L17 (41.672, -6.723)-(38.703, -6.723); L18 (38.703, -6.723)-(38.703, 0.37); L19 (38.703, 0.37)-(41.672, 0.37); L20 (41.672, 0.37)-(41.672, -6.723); L21 (24.023, -6.723)-(17.508, -6.723); L22 (17.508, -6.723)-(17.508, 0.37); L23 (17.508, 0.37)-(24.023, 0.37); L24 (24.023, 0.37)-(24.023, -6.723); L25 (77.327, -6.723)-(70.812, -6.723); L26 (70.812, -6.723)-(70.812, 0.37); L27 (70.812, 0.37)-(77.327, 0.37); L28 (69.822, 0.37)-(69.822, -6.723); L29 (67.596, 0.37)-(69.822, 0.37); L30 (69.822, -6.723)-(67.596, -6.723); L31 (67.596, -6.723)-(67.596, 0.37); L32 (63.885, 0.37)-(63.885, -6.723); L33 (57.534, -6.723)-(57.534, 0.37); L34 (57.534, 0.37)-(63.885, 0.37); L35 (63.885, -6.723)-(57.534, -6.723); L36 (77.327, 0.37)-(77.327, -6.723); L37 (85.162, -6.723)-(85.162, 0.37); L38 (85.162, 0.37)-(89.863, 0.37); L39 (89.863, -6.723)-(85.162, -6.723); L40 (89.863, 0.37)-(89.863, -6.723); L41 (92.007, -6.723)-(92.007, 0.37); L42 (92.007, 0.37)-(94.976, 0.37); L43 (94.976, 0.37)-(94.976, -6.723); L44 (94.976, -6.723)-(92.007, -6.723); L45 (97.863, 0.37)-(97.863, -6.723); L46 (104.79, -6.723)-(104.79, 0.37); L47 (104.79, 0.37)-(97.863, 0.37); L48 (97.863, -6.723)-(104.79, -6.723); L49 (126.543, -6.723)-(120.028, -6.723); L50 (120.028, -6.723)-(120.028, 0.37); L51 (120.028, 0.37)-(126.543, 0.37); L52 (119.038, 0.37)-(119.038, -6.723); L53 (116.812, 0.37)-(119.038, 0.37); L54 (119.038, -6.723)-(116.812, -6.723); L55 (116.812, -6.723)-(116.812, 0.37); L56 (113.1, 0.37)-(113.1, -6.723); L57 (106.75, -6.723)-(106.75, 0.37); L58 (106.75, 0.37)-(113.1, 0.37); L59 (113.1, -6.723)-(106.75, -6.723); L60 (126.543, 0.37)-(126.543, -6.723); L61 (134.378, -6.723)-(134.378, 0.37); L62 (134.378, 0.37)-(139.079, 0.37); L63 (139.079, -6.723)-(134.378, -6.723); L64 (139.079, 0.37)-(139.079, -6.723)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; 1 further point
  constraints: 1096 end point, 274 parallel, 137 horizontal, 137 perpendicular, 4 point on line
extrude "Extrusion139" cut sketch "Sketch139" distance "d327" = 0.25; taper "d328" = 0 deg
sketch "Sketch140"
  geometry: L1 (4.882, 0.25)-(15.983, 0.25); L2 (15.983, 0.25)-(15.983, -6.392); L3 (15.983, -6.392)-(4.882, -6.392); L4 (4.882, -6.392)-(4.882, 0.25); L5 (19.493, -6.392)-(21.676, -6.392); L6 (21.676, -6.392)-(21.676, 0.25); L7 (21.676, 0.25)-(19.493, 0.25); L8 (19.493, 0.25)-(19.493, -6.392); L9 (28.602, -6.392)-(33.725, -6.392); L10 (33.725, -6.392)-(33.725, 0.25); L11 (33.725, 0.25)-(28.602, 0.25); L12 (28.602, 0.25)-(28.602, -6.392); L13 (35.908, -6.392)-(37.046, -6.392); L14 (37.046, -6.392)-(37.046, 0.25); L15 (37.046, 0.25)-(35.908, 0.25); L16 (35.908, 0.25)-(35.908, -6.392); L17 (41.79, 0.25)-(49.855, 0.25); L18 (49.855, 0.25)-(49.855, -6.392); L19 (49.855, -6.392)-(41.79, -6.392); L20 (41.79, -6.392)-(41.79, 0.25); L21 (57.066, -6.392)-(61.62, -6.392); L22 (61.62, -6.392)-(61.62, 0.25); L23 (61.62, 0.25)-(57.066, 0.25); L24 (57.066, 0.25)-(57.066, -6.392); L25 (118.982, -6.392)-(123.536, -6.392); L26 (123.536, -6.392)-(123.536, 0.25); L27 (123.536, 0.25)-(118.982, 0.25); L28 (118.982, 0.25)-(118.982, -6.392); L29 (103.706, 0.25)-(111.771, 0.25); L30 (111.771, 0.25)-(111.771, -6.392); L31 (111.771, -6.392)-(103.706, -6.392); L32 (90.517, 0.25)-(90.517, -6.392); L33 (90.517, -6.392)-(95.641, -6.392); L34 (95.641, 0.25)-(90.517, 0.25); L35 (95.641, -6.392)-(95.641, 0.25); L36 (97.823, 0.25)-(97.823, -6.392); L37 (97.823, -6.392)-(98.962, -6.392); L38 (98.962, 0.25)-(97.823, 0.25); L39 (103.706, -6.392)-(103.706, 0.25); L40 (98.962, -6.392)-(98.962, 0.25); L41 (83.591, -6.392)-(83.591, 0.25); L42 (81.409, -6.392)-(83.591, -6.392); L43 (81.409, 0.25)-(81.409, -6.392); L44 (77.898, 0.25)-(77.898, -6.392); L45 (77.898, -6.392)-(66.797, -6.392); L46 (66.797, -6.392)-(66.797, 0.25); L47 (66.797, 0.25)-(77.898, 0.25); L48 (83.591, 0.25)-(81.409, 0.25); L49 (69.727, -13.026)-(74.281, -13.026); L50 (74.281, -13.026)-(74.281, -6.385); L51 (74.281, -6.385)-(69.727, -6.385); L52 (69.727, -6.385)-(69.727, -13.026); L53 (54.451, -6.385)-(62.516, -6.385); L54 (62.516, -6.385)-(62.516, -13.026); L55 (62.516, -13.026)-(54.451, -13.026); L56 (41.263, -6.385)-(41.263, -13.026); L57 (41.263, -13.026)-(46.386, -13.026); L58 (46.386, -6.385)-(41.263, -6.385); L59 (46.386, -13.026)-(46.386, -6.385); L60 (48.569, -6.385)-(48.569, -13.026); L61 (48.569, -13.026)-(49.707, -13.026); L62 (49.707, -6.385)-(48.569, -6.385); L63 (54.451, -13.026)-(54.451, -6.385); L64 (49.707, -13.026)-(49.707, -6.385)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
  constraints: 616 end point, 154 parallel, 77 horizontal, 77 perpendicular
extrude "Extrusion140" cut sketch "Sketch140" distance "d329" = 0.25; taper "d330" = 0 deg
sketch "Sketch141"
  geometry: L1 (6.662, 0.459)-(18.247, 0.459); L2 (18.247, 0.459)-(18.247, -8.486); L3 (18.247, -8.486)-(6.662, -8.486); L4 (6.662, -8.486)-(6.662, 0.459); L5 (24.113, -8.486)-(27.779, -8.486); L6 (27.779, -8.486)-(27.779, 0.459); L7 (27.779, 0.459)-(24.113, 0.459); L8 (24.113, 0.459)-(24.113, -8.486); L9 (35.551, 0.459)-(37.604, 0.459); L10 (37.604, 0.459)-(37.604, -8.486); L11 (37.604, -8.486)-(35.551, -8.486); L12 (35.551, -8.486)-(35.551, 0.459); L13 (42.884, -8.486)-(55.055, -8.486); L14 (55.055, -8.486)-(55.055, 0.459); L15 (55.055, 0.459)-(42.884, 0.459); L16 (42.884, 0.459)-(42.884, -8.486); L17 (20.74, -25.644)-(33.352, -25.644); L18 (33.352, -25.644)-(33.352, -17.139); L19 (33.352, -17.139)-(20.74, -17.139); L20 (20.74, -17.139)-(20.74, -25.644); L21 (42.884, -34.736)-(55.055, -34.736); L22 (55.055, -34.736)-(55.055, -42.655); L23 (55.055, -42.655)-(42.884, -42.655); L24 (42.884, -42.655)-(42.884, -34.736); L25 (36.578, -50.72)-(27.046, -50.72); L26 (27.046, -50.72)-(27.046, -42.655); L27 (27.046, -42.655)-(36.578, -42.655); L28 (36.578, -42.655)-(36.578, -50.72); L29 (39.217, -50.72)-(52.415, -50.72); L30 (52.415, -50.72)-(52.415, -59.079); L31 (52.415, -59.079)-(39.217, -59.079); L32 (39.217, -59.079)-(39.217, -50.72); L33 (36.578, -59.079)-(39.217, -59.079); L34 (39.217, -59.079)-(39.217, -67.584); L35 (39.217, -67.584)-(36.578, -67.584); L36 (36.578, -67.584)-(36.578, -59.079); L37 (53.295, -67.584)-(56.522, -67.584); L38 (56.522, -67.584)-(56.522, -59.079); L39 (56.522, -59.079)-(53.295, -59.079); L40 (53.295, -59.079)-(53.295, -67.584); L41 (45.816, -67.584)-(44.643, -67.584); L42 (44.643, -67.584)-(44.643, -59.079); L43 (44.643, -59.079)-(45.816, -59.079); L44 (45.816, -59.079)-(45.816, -67.584); L45 (33.352, -59.079)-(31.812, -59.079); L46 (31.812, -59.079)-(31.812, -50.72); L47 (31.812, -50.72)-(33.352, -50.72); L48 (33.352, -50.72)-(33.352, -59.079); L49 (54.908, -50.72)-(52.415, -50.72); L50 (52.415, -50.72)-(52.415, -42.655); L51 (52.415, -42.655)-(54.908, -42.655); L52 (54.908, -42.655)-(54.908, -50.72); L53 (40.244, -42.655)-(44.643, -42.655); L54 (44.643, -42.655)-(44.643, -50.72); L55 (44.643, -50.72)-(40.244, -50.72); L56 (40.244, -50.72)-(40.244, -42.655); L57 (35.551, -34.736)-(31.812, -34.736); L58 (31.812, -34.736)-(31.812, -42.655); L59 (31.812, -42.655)-(35.551, -42.655); L60 (35.551, -42.655)-(35.551, -34.736); L61 (22.353, -34.736)-(24.113, -34.736); L62 (24.113, -34.736)-(24.113, -42.655); L63 (24.113, -42.655)-(22.353, -42.655); L64 (22.353, -42.655)-(22.353, -34.736)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; 1 further point
  constraints: 216 end point, 54 parallel, 27 horizontal, 27 perpendicular, 16 point on line, 3 midpoint
extrude "Extrusion141" cut sketch "Sketch141" distance "d331" = 0.25; taper "d332" = 0 deg
sketch "Sketch142"
  geometry: L1 (-1.389, -0.704)-(-2.778, -1.409) reference; L2 (-1.974, 24.394)-(-2.278, 24.394) reference; L3 (-2.528, 4.163)-(-2.528, 1.524) reference; L4 (-2.278, 24.394)-(-2.278, -1.155); L5 (-1.974, 24.394)-(-1.974, -1.001); 1 further point
  constraints: 4 end point, 2 parallel, 2 point on line
extrude "Extrusion142" cut sketch "Sketch142" distance "d333" = 0.5; taper "d334" = 0 deg
sketch "Sketch143"
  geometry: L1 (16.815, 2.789)-(16.218, 1.612) reference; L2 (16.815, 2.789)-(-9.5, 2.789) reference; L3 (-9, 2.289)-(-9, 1.961) reference; L4 (-9, 1.961)-(16.395, 1.961); L5 (-9, 2.289)-(16.561, 2.289); 1 further point
  constraints: 4 end point, 2 point on line, 1 parallel, 1 perpendicular
extrude "Extrusion143" cut sketch "Sketch143" distance "d335" = 0.5; taper "d336" = 0 deg
sketch "Sketch144"
  geometry: L1 (-60.096, 3.391)-(-51.005, 3.391); L2 (-51.005, 3.391)-(-51.005, 12.482); L3 (-51.005, 12.482)-(-60.096, 12.482); L4 (-60.096, 12.482)-(-60.096, 3.391); L5 (-51.005, 15.446)-(-60.096, 15.446); L6 (-60.096, 15.446)-(-60.096, 19.794); L7 (-60.096, 19.794)-(-51.005, 19.794); L8 (-51.005, 19.794)-(-51.005, 15.446); L9 (-51.005, 47.859)-(-60.096, 47.859); L10 (-60.096, 47.859)-(-60.096, 46.673); L11 (-60.096, 46.673)-(-51.005, 46.673); L12 (-51.005, 46.673)-(-51.005, 47.859); L13 (-60.096, 44.795)-(-51.005, 44.795); L14 (-51.005, 44.795)-(-51.005, 36.791); L15 (-51.005, 36.791)-(-60.096, 36.791); L16 (-60.096, 36.791)-(-60.096, 44.795); L17 (-51.598, 32.443)-(-60.096, 32.443); L18 (-60.096, 32.443)-(-60.096, 23.747); L19 (-60.096, 23.747)-(-51.598, 23.747); L20 (-51.598, 23.747)-(-51.598, 32.443); L21 (-42.902, 48.946)-(-51.005, 48.946); L22 (-51.005, 48.946)-(-51.005, 51.12); L23 (-51.005, 51.12)-(-42.902, 51.12); L24 (-42.902, 51.12)-(-42.902, 48.946); L25 (-51.005, 44.795)-(-42.309, 44.795); L26 (-42.309, 44.795)-(-42.309, 39.953); L27 (-42.309, 39.953)-(-51.005, 39.953); L28 (-51.005, 39.953)-(-51.005, 44.795); L29 (-42.309, 36.791)-(-51.598, 36.791); L30 (-51.598, 36.791)-(-51.598, 28.095); L31 (-51.598, 28.095)-(-42.309, 28.095); L32 (-42.309, 28.095)-(-42.309, 36.791); L33 (-51.005, 24.567)-(-42.309, 24.567); L34 (-42.309, 24.567)-(-42.309, 21.017); L35 (-42.309, 21.017)-(-51.005, 21.017); L36 (-51.005, 21.017)-(-51.005, 24.567); L37 (-51.005, 14.392)-(-42.309, 14.392); L38 (-42.309, 14.392)-(-42.309, 5.794); L39 (-42.309, 5.794)-(-51.005, 5.794); L40 (-51.005, 5.794)-(-51.005, 14.392); L41 (-42.309, 15.446)-(-33.686, 15.446); L42 (-33.686, 15.446)-(-33.686, 19.203); L43 (-33.686, 19.203)-(-42.309, 19.203); L44 (-42.309, 19.203)-(-42.309, 15.446); L45 (-34.238, 7.936)-(-42.309, 7.936); L46 (-42.309, 7.936)-(-42.309, -1.463); L47 (-42.309, -1.463)-(-34.238, -1.463); L48 (-34.238, -1.463)-(-34.238, 7.936); L49 (-42.309, 29.931)-(-33.686, 29.931); L50 (-33.686, 29.931)-(-33.686, 37.976); L51 (-33.686, 37.976)-(-42.309, 37.976); L52 (-42.309, 37.976)-(-42.309, 29.931); L53 (-34.238, 42.374)-(-42.309, 42.374); L54 (-42.309, 42.374)-(-42.309, 43.183); L55 (-42.309, 43.183)-(-34.238, 43.183); L56 (-34.238, 43.183)-(-34.238, 42.374); L57 (-25.325, 42.374)-(-34.238, 42.374); L58 (-34.238, 42.374)-(-34.238, 35.847); L59 (-34.238, 35.847)-(-25.325, 35.847); L60 (-25.325, 35.847)-(-25.325, 42.374); L61 (-34.238, 32.443)-(-25.325, 32.443); L62 (-25.325, 32.443)-(-25.325, 30.877); L63 (-25.325, 30.877)-(-34.238, 30.877); L64 (-34.238, 30.877)-(-34.238, 32.443)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; 1 further point
  constraints: 248 end point, 62 parallel, 31 horizontal, 31 perpendicular, 10 point on line, 2 midpoint
extrude "Extrusion144" cut sketch "Sketch144" distance "d337" = 0.25; taper "d338" = 0 deg
sketch "Sketch145"
  geometry: L1 (9.839, -0.553)-(5.344, -0.553); L2 (5.344, -0.553)-(5.344, -6.546); L3 (5.344, -6.546)-(9.839, -6.546); L4 (9.839, -6.546)-(9.839, -0.553); L5 (15.233, -6.546)-(25.722, -6.546); L6 (25.722, -6.546)-(25.722, -0.553); L7 (25.722, -0.553)-(15.233, -0.553); L8 (15.233, -0.553)-(15.233, -6.546); L9 (31.266, -6.546)-(33.064, -6.546); L10 (33.064, -6.546)-(33.064, -0.553); L11 (33.064, -0.553)-(31.266, -0.553); L12 (31.266, -0.553)-(31.266, -6.546); L13 (39.656, -0.553)-(41.305, -0.553); L14 (41.305, -0.553)-(41.305, -6.546); L15 (41.305, -6.546)-(39.656, -6.546); L16 (39.656, -6.546)-(39.656, -0.553); L17 (49.995, -0.553)-(59.285, -0.553); L18 (59.285, -0.553)-(59.285, -6.546); L19 (59.285, -6.546)-(49.995, -6.546); L20 (49.995, -6.546)-(49.995, -0.553); L21 (68.875, -0.553)-(69.924, -0.553); L22 (69.924, -0.553)-(69.924, -6.546); L23 (69.924, -6.546)-(68.875, -6.546); L24 (68.875, -6.546)-(68.875, -0.553); L25 (72.321, -0.553)-(79.064, -0.553); L26 (79.064, -0.553)-(79.064, -6.546); L27 (79.064, -6.546)-(72.321, -6.546); L28 (72.321, -6.546)-(72.321, -0.553); L29 (84.907, -0.553)-(87.305, -0.553); L30 (87.305, -0.553)-(87.305, -6.546); L31 (87.305, -6.546)-(84.907, -6.546); L32 (84.907, -6.546)-(84.907, -0.553); L33 (92.099, -6.546)-(100.191, -6.546); L34 (100.191, -6.546)-(100.191, -0.553); L35 (100.191, -0.553)-(92.099, -0.553); L36 (92.099, -0.553)-(92.099, -6.546); L37 (105.135, -6.546)-(107.683, -6.546); L38 (107.683, -6.546)-(107.683, -0.553); L39 (107.683, -0.553)-(105.135, -0.553); L40 (105.135, -0.553)-(105.135, -6.546); L41 (109.93, -0.553)-(116.373, -0.553); L42 (116.373, -0.553)-(116.373, -6.546); L43 (116.373, -6.546)-(109.93, -6.546); L44 (109.93, -6.546)-(109.93, -0.553); L45 (124.764, -6.546)-(125.513, -6.546); L46 (125.513, -6.546)-(125.513, -0.553); L47 (125.513, -0.553)-(124.764, -0.553); L48 (124.764, -0.553)-(124.764, -6.546); L49 (3.396, 44.548)-(8.043, 44.548); L50 (8.043, 44.548)-(8.043, 52.153); L51 (8.043, 52.153)-(3.396, 52.153); L52 (3.396, 52.153)-(3.396, 44.548); L53 (15.233, 44.548)-(18.634, 44.548); L54 (18.634, 44.548)-(18.634, 52.153); L55 (18.634, 52.153)-(15.233, 52.153); L56 (15.233, 52.153)-(15.233, 44.548); L57 (27.882, 52.153)-(29.7, 52.153); L58 (29.7, 52.153)-(29.7, 44.548); L59 (29.7, 44.548)-(27.882, 44.548); L60 (27.882, 44.548)-(27.882, 52.153); L61 (31.266, 44.548)-(42.11, 44.548); L62 (42.11, 44.548)-(42.11, 52.153); L63 (42.11, 52.153)-(31.266, 52.153); L64 (31.266, 52.153)-(31.266, 44.548)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; 1 further point
  constraints: 704 end point, 176 parallel, 88 horizontal, 88 perpendicular, 15 point on line, 4 midpoint
extrude "Extrusion145" cut sketch "Sketch145" distance "d339" = 0.25; taper "d340" = 0 deg
sketch "Sketch146"
  geometry: L1 (-113.739, 149.54)-(-113.739, 117.97) reference; L2 (-113.739, 117.97)-(-132.244, 117.97) reference; L3 (-132.244, 117.97)-(-132.244, 149.54) reference; L4 (-132.244, 149.54)-(-113.739, 149.54) reference; L5 (-115, 148)-(-131, 148); L6 (-131, 148)-(-131, 119); L7 (-131, 119)-(-115, 119); L8 (-115, 119)-(-115, 148); L9 (-115, 133.5)-(-131, 133.5); L10 (-131, 133.5)-(-131, 134.332); L11 (-131, 134.332)-(-115, 134.332); L12 (-115, 134.332)-(-115, 133.5); L13 (-131, 133.5)-(-115, 133.5); L14 (-115, 133.5)-(-115, 132); L15 (-115, 132)-(-131, 132); L16 (-131, 132)-(-131, 133.5); 1 further point
  constraints: 24 end point, 6 parallel, 3 horizontal, 3 perpendicular, 2 point on line, 1 midpoint
extrude "Extrusion146" join sketch "Sketch146" distance "d341" = 2; taper "d342" = 0 deg
sketch "Sketch147"
  geometry: L1 (115, 134.332)-(115, 148) reference; L2 (115, 148)-(131, 148) reference; L3 (131, 148)-(131, 134.332) reference; L4 (131, 134.332)-(115, 134.332) reference; L5 (113.739, 117.97)-(113.739, 149.54) reference; L6 (132.244, 149.54)-(132.244, 117.97) reference; L7 (113.739, 149.54)-(132.244, 149.54) reference; L8 (113.739, 133)-(132.244, 133); 1 further point
  constraints: 2 end point, 2 point on line, 1 parallel
extrude "Extrusion147" join sketch "Sketch147" distance "d343" = 1.25; taper "d344" = 0 deg
sketch "Sketch148"
  geometry: L1 (-131, 134.332)-(-131, 148) reference; L2 (-131, 148)-(-115, 148) reference; L3 (-115, 148)-(-115, 134.332) reference; L4 (-115, 132)-(-115, 119) reference; L5 (-115, 119)-(-131, 119) reference; L6 (-131, 119)-(-131, 132) reference; L7 (-123, 148)-(-123.589, 148); L8 (-123.589, 148)-(-123.589, 119); L9 (-123.589, 119)-(-123, 119); L10 (-123, 119)-(-123, 148); L11 (-123, 119)-(-122.377, 119); L12 (-122.377, 119)-(-122.377, 148); L13 (-122.377, 148)-(-123, 148); L14 (-123, 148)-(-123, 119); L15 (-131, 141.166)-(-115, 141.166); L16 (-115, 141.166)-(-115, 140.221); L17 (-115, 140.221)-(-131, 140.221); L18 (-131, 140.221)-(-131, 141.166); L19 (-131, 126)-(-115, 126); L20 (-115, 126)-(-115, 125); L21 (-115, 125)-(-131, 125); L22 (-131, 125)-(-131, 126); 1 further point
  constraints: 32 end point, 8 parallel, 5 point on line, 4 horizontal, 4 perpendicular, 2 midpoint
extrude "Extrusion148" join sketch "Sketch148" distance "d345" = 1.25; taper "d346" = 0 deg
sketch "Sketch149"
  geometry: L1 (123.589, 134.332)-(122.377, 134.332) reference; L2 (123.589, 134.332)-(123.589, 140.221) reference; L3 (123.589, 140.221)-(131, 140.221) reference; L4 (131, 141.166)-(131, 140.221) reference; L5 (131, 141.166)-(123.589, 141.166) reference; L6 (123.589, 141.166)-(123.589, 148) reference; L7 (122.377, 148)-(123.589, 148) reference; L8 (122.377, 148)-(122.377, 141.166) reference; L9 (122.377, 141.166)-(115, 141.166) reference; L10 (115, 140.221)-(115, 141.166) reference; L11 (115, 140.221)-(122.377, 140.221) reference; L12 (122.377, 140.221)-(122.377, 134.332) reference; 1 further point
extrude "Extrusion149" join sketch "Sketch149" distance "d347" = 1.25; taper "d348" = 0 deg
